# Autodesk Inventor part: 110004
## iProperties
Shininess: 64.0
Length Units: 11272
Angle Units: 11279
Time Units: 11290
Mass Units: 11286
Length Display Precision: 3
Angle Display Precision: 2
Compacted: True
Part Number: 110004
Document SubType Name: Modeling
Created: 2004-06
Designer: jpittman
Manufacturer: Standard
Standards Organization: Custom
Density: 0.0
Volumn: 0.0
Area: 0.0
PropertySet Name: Model Information
Control State: 0
Master: False
Checked Out: False
Translation Standard: STEP AP203
File Name: 110004
Preprocessor: PRO/ENGINEER BY PARAMETRIC TECHNOLOGY CORPORATION, 2001150
Postprocessor: Build: 081d, Release: 8 SP1 - Date: Tue 01/26/2004
Sent Units: INCHES
Uncertainty: 0.00019624199077060002
Author: jpittman
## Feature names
1. Base1
